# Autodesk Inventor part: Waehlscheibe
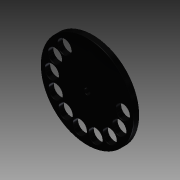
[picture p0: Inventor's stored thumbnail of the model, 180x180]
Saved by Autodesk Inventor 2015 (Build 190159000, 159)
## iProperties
Created: 2015-01
Part Number: Waehlscheibe
Material: Thermoplastisches Harz
Document SubType Name: Modeling
Designer: Manuel
Density: 1.28 g/cm^3
Appearance: Glatt - schwarz
Author: Manuel
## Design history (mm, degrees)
sketch "Skizze1"
  geometry: C1 r 2.5 at (0, 0); C2 r 40 at (0, 0); C3 r 23 at (0, 0); C4 r 6 at (-30.478, 0); C5 r 6 at (-27.496, -13.148); C6 r 6 at (-19.134, -23.723); C7 r 6 at (-7.029, -29.656); C8 r 6 at (6.452, -29.787); C9 r 6 at (18.671, -24.09); C10 r 6 at (27.236, -13.678); C11 r 6 at (30.472, -0.591); C12 r 6 at (27.746, 12.612); C13 r 6 at (19.591, 23.347); 1 further point
  constraints: 13 centre point, 3 coincident, 19 other
  dimensions: "d0" = 5 diameter of C1; "d1" = 80 diameter of C2; "d2" = 46 diameter of C3; "d3" = 12 diameter of C4; "d6" = 230 deg dimension on point (0, 0) C4.centre C13.centre
extrude "Extrusion1" new body sketch "Skizze1" distance "d8" = 5; taper "d9" = 0 deg
fillet "Rundung2" dims "d11" = 0.5
fillet "Rundung3" dims "d12" = 0.5
fillet "Rundung4" dims "d13" = 0.5
node "Volumenkörper1"
